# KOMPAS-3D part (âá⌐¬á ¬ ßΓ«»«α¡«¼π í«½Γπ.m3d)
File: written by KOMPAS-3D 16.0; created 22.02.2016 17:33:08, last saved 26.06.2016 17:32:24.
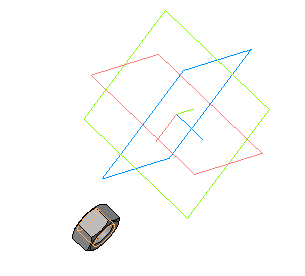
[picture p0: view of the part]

Expressions: М10x1-6H
Referenced files in E:\Libs\PartLib\DATA\vault\Methods\Kompas\3D\: PLib_Nut_OST92_900.m3d
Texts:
  Гайка М10x1-6H ГОСТ 15521-70
  bcut1
  hole1
  hcut1
  hole2
  cut1
  (-) Гайка М10x1-6H ГОСТ 15521-70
